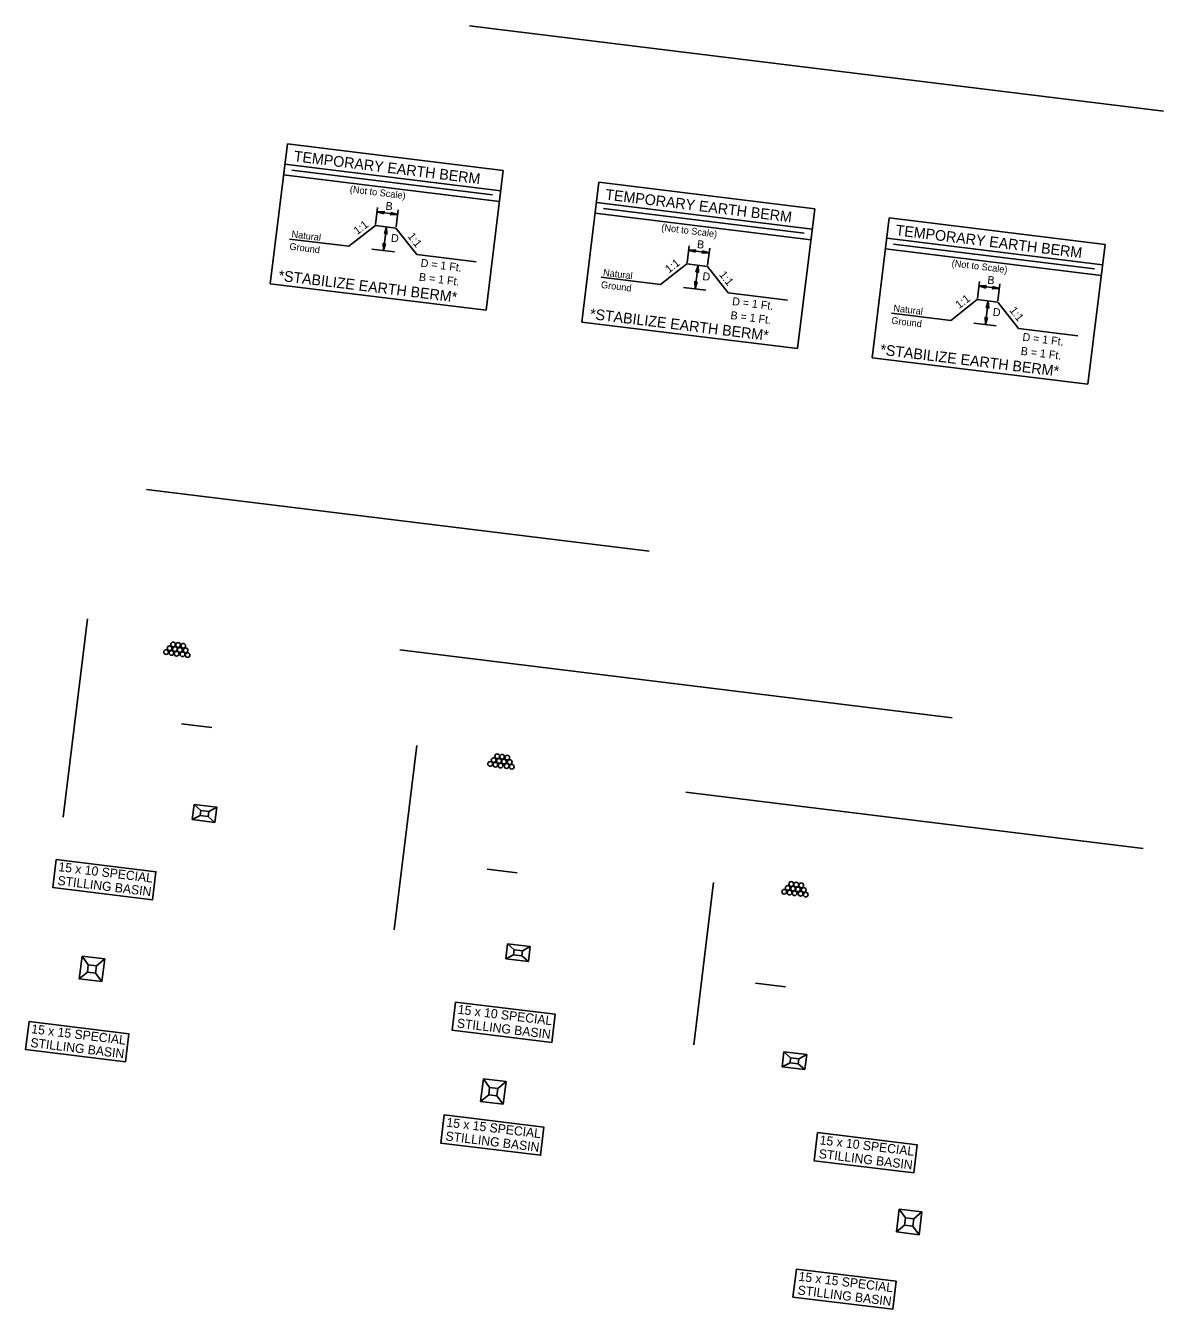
# Model space of a CAD drawing. Extents: x 2470000 to 2520000, y 340000 to 380000.
# Drawn here: x 2481272 to 2482019, y 373431 to 374273 of the extents above; entities that cross this region are included whole.
import ezdxf

# ---------------------------------------------------------------- set-up
doc = ezdxf.new("R2010")
doc.units = 0
for name, color, linetype in [('Earth Berm for Slope Drains Final', 7, 'Continuous'), ('Exist Property Owner Number CELL', 7, 'Continuous'), ('Exist Property Owner Text', 7, 'Continuous'), ('Exist Right of Way Easement Line', 7, 'Continuous'), ('Exist Right of Way Line', 7, 'Continuous'), ('Matchline', 7, 'Continuous'), ('Matchline Text', 7, 'Continuous'), ('Prop Dimension', 7, 'Continuous'), ('Prop Dimension Text', 7, 'Continuous'), ('Prop DSN Text', 7, 'Continuous'), ('Prop Grid Mask', 7, 'Continuous'), ('Prop Guardrail Attenuator CELL', 7, 'Continuous'), ('Prop Horizontal Alignment Tick Label', 7, 'Continuous'), ('Prop Lane Arrow CELL', 7, 'Continuous'), ('Prop Noise Wall', 7, 'Continuous'), ('Prop North Arrow NAD83 for Plan Sheets CELL', 7, 'Continuous'), ('Prop Superelevation  Arrow CELL', 7, 'Continuous'), ('Prop Superelevation Label', 7, 'Continuous'), ('Prop Terminator CELL', 7, 'Continuous'), ('Scratch_Level_5', 7, 'Continuous'), ('Scratch_Level_9', 7, 'Continuous'), ('Sheet Block Title CELL', 7, 'Continuous'), ('Sheet Sticker Incomplete CELL', 7, 'Continuous'), ('Sheet Sticker Preliminary CELL', 7, 'Continuous'), ('Special Stilling Basin 15 x 10 Note Final CELL', 7, 'Continuous'), ('Special Stilling Basin 15 x 15 Final CELL', 7, 'Continuous'), ('Special Stilling Basin 15 x 15 Note Both CELL', 7, 'Continuous'), ('Special Stilling Basin 15 x 15 Note Final CELL', 7, 'Continuous')]:
    doc.layers.add(name, color=color, linetype=linetype)

msp = doc.modelspace()

# ---------------------------------------------------------------- linework, layer by layer
at = {"layer": 'Earth Berm for Slope Drains Final'}
msp.add_line((2481705.55, 373770.06), (2482005.91, 373733.14), dxfattribs=at)
at = {"layer": 'Exist Property Owner Number CELL'}
msp.add_line((2481723.92, 373710.81), (2481710.8, 373604.14), dxfattribs=at)
at = {"layer": 'Exist Property Owner Text'}
for centre in [(2481774.85, 373709.75), (2481778.09, 373709.39), (2481770.22, 373704.69), (2481772.54, 373707.22), (2481773.72, 373704.15), (2481776.03, 373706.68), (2481777.07, 373703.64), (2481779.25, 373706.19), (2481781.01, 373703.31), (2481781.45, 373708.88), (2481783.05, 373705.88), (2481784.37, 373702.79)]:
    msp.add_circle(centre, 1.55, dxfattribs=at)
at = {"layer": 'Exist Right of Way Easement Line'}
msp.add_line((2481751.31, 373644.75), (2481771.16, 373642.31), dxfattribs=at)
at = {"layer": 'Exist Right of Way Line'}
for p, q in [((2481768.87, 373589.77), (2481770.1, 373599.7)), ((2481774.43, 373595.7), (2481770.1, 373599.7)), ((2481770.1, 373599.7), (2481784.99, 373597.86)), ((2481774.04, 373592.48), (2481774.43, 373595.7)), ((2481774.43, 373595.7), (2481779.82, 373595.01)), ((2481779.82, 373595.01), (2481779.43, 373591.81)), ((2481779.83, 373595.04), (2481784.99, 373597.86)), ((2481784.99, 373597.86), (2481783.77, 373587.94)), ((2481768.89, 373589.77), (2481774.08, 373592.46)), ((2481783.79, 373587.93), (2481768.89, 373589.77)), ((2481779.43, 373591.81), (2481774.08, 373592.46)), ((2481779.43, 373591.81), (2481783.77, 373587.94))]:
    msp.add_line(p, q, dxfattribs=at)
at = {"layer": 'Matchline'}
msp.add_line((2481312.82, 373883.8), (2481296.82, 373753.63), dxfattribs=at)
at = {"layer": 'Matchline Text'}
msp.add_line((2481374.5, 373814.87), (2481394.35, 373812.43), dxfattribs=at)
at = {"layer": 'Prop Dimension'}
msp.add_lwpolyline([(2481274.46, 373619.51), (2481339.97, 373611.46), (2481337.71, 373593.06), (2481272.2, 373601.11)], close=True, dxfattribs=at)
at = {"layer": 'Prop Dimension Text'}
for p, q in [((2481381.56, 373752.01), (2481382.79, 373761.94)), ((2481387.12, 373757.94), (2481382.79, 373761.94)), ((2481382.79, 373761.94), (2481397.67, 373760.1)), ((2481381.58, 373752.01), (2481386.77, 373754.7)), ((2481386.73, 373754.72), (2481387.12, 373757.94)), ((2481392.11, 373754.05), (2481386.77, 373754.7)), ((2481387.12, 373757.94), (2481392.51, 373757.25)), ((2481392.51, 373757.25), (2481392.11, 373754.05)), ((2481392.11, 373754.05), (2481396.46, 373750.18)), ((2481392.52, 373757.28), (2481397.67, 373760.1)), ((2481397.67, 373760.1), (2481396.46, 373750.18)), ((2481396.48, 373750.17), (2481381.58, 373752.01))]:
    msp.add_line(p, q, dxfattribs=at)
at = {"layer": 'Prop DSN Text'}
for centre in [(2481364.4, 373861.89), (2481366.71, 373864.42), (2481367.89, 373861.36), (2481369.02, 373866.95), (2481370.2, 373863.89), (2481371.25, 373860.84), (2481372.27, 373866.59), (2481373.43, 373863.39), (2481375.63, 373866.08), (2481377.23, 373863.08), (2481375.18, 373860.51), (2481378.54, 373859.99)]:
    msp.add_circle(centre, 1.55, dxfattribs=at)
at = {"layer": 'Prop Grid Mask'}
msp.add_lwpolyline([(2481292.26, 373725.86), (2481357.76, 373717.81), (2481355.5, 373699.41), (2481289.99, 373707.46)], close=True, dxfattribs=at)
at = {"layer": 'Prop Guardrail Attenuator CELL'}
msp.add_line((2481517.94, 373863.3), (2481880.55, 373818.73), dxfattribs=at)
at = {"layer": 'Prop Horizontal Alignment Tick Label'}
msp.add_line((2481575.12, 373719.42), (2481594.97, 373716.98), dxfattribs=at)
at = {"layer": 'Prop Lane Arrow CELL'}
for p, q in [((2481587.4, 373660.64), (2481588.63, 373670.57)), ((2481592.96, 373666.57), (2481588.63, 373670.57)), ((2481588.63, 373670.57), (2481603.52, 373668.73)), ((2481598.37, 373665.91), (2481603.52, 373668.73)), ((2481603.52, 373668.73), (2481602.31, 373658.81)), ((2481587.43, 373660.64), (2481592.61, 373663.33)), ((2481602.32, 373658.8), (2481587.43, 373660.64)), ((2481592.58, 373663.35), (2481592.96, 373666.57)), ((2481597.96, 373662.68), (2481592.61, 373663.33)), ((2481592.96, 373666.57), (2481598.35, 373665.88)), ((2481598.35, 373665.88), (2481597.96, 373662.68)), ((2481597.96, 373662.68), (2481602.31, 373658.81))]:
    msp.add_line(p, q, dxfattribs=at)
at = {"layer": 'Prop Noise Wall'}
for centre in [(2481581.8, 373793.61), (2481577.18, 373788.55), (2481579.49, 373791.08), (2481580.67, 373788.01), (2481582.98, 373790.54), (2481584.03, 373787.49), (2481585.05, 373793.25), (2481586.2, 373790.05), (2481587.96, 373787.16), (2481588.4, 373792.73), (2481590.01, 373789.74), (2481591.32, 373786.65)]:
    msp.add_circle(centre, 1.55, dxfattribs=at)
at = {"layer": 'Prop North Arrow NAD83 for Plan Sheets CELL'}
msp.add_line((2481351.57, 373968.69), (2481681.64, 373928.12), dxfattribs=at)
at = {"layer": 'Prop Superelevation  Arrow CELL'}
msp.add_lwpolyline([(2481554.46, 373632.28), (2481619.96, 373624.23), (2481617.7, 373605.83), (2481552.2, 373613.88)], close=True, dxfattribs=at)
at = {"layer": 'Prop Superelevation Label'}
for p, q in [((2481570.88, 373567.04), (2481572.72, 373581.93)), ((2481576.84, 373576.23), (2481572.72, 373581.93)), ((2481572.72, 373581.93), (2481587.61, 373580.09)), ((2481576.26, 373571.4), (2481576.84, 373576.23)), ((2481576.84, 373576.23), (2481582.23, 373575.52)), ((2481582.25, 373575.56), (2481587.61, 373580.09)), ((2481587.61, 373580.09), (2481585.79, 373565.2)), ((2481570.91, 373567.03), (2481576.29, 373571.37)), ((2481581.64, 373570.71), (2481576.29, 373571.37)), ((2481582.23, 373575.52), (2481581.64, 373570.71)), ((2481581.64, 373570.71), (2481585.79, 373565.2)), ((2481585.8, 373565.19), (2481570.91, 373567.03))]:
    msp.add_line(p, q, dxfattribs=at)
at = {"layer": 'Prop Terminator CELL'}
for p, q in [((2481307.37, 373647.55), (2481309.21, 373662.45)), ((2481313.33, 373656.74), (2481309.21, 373662.45)), ((2481309.21, 373662.45), (2481324.1, 373660.61)), ((2481318.73, 373656.08), (2481324.1, 373660.61)), ((2481324.1, 373660.61), (2481322.27, 373645.72)), ((2481307.4, 373647.55), (2481312.78, 373651.89)), ((2481312.75, 373651.91), (2481313.33, 373656.74)), ((2481318.13, 373651.23), (2481312.78, 373651.89)), ((2481313.33, 373656.74), (2481318.72, 373656.04)), ((2481318.72, 373656.04), (2481318.13, 373651.23)), ((2481322.29, 373645.71), (2481307.4, 373647.55)), ((2481318.13, 373651.23), (2481322.27, 373645.72))]:
    msp.add_line(p, q, dxfattribs=at)
at = {"layer": 'Scratch_Level_5'}
msp.add_line((2481529.11, 373800.58), (2481514.25, 373679.71), dxfattribs=at)
at = {"layer": 'Scratch_Level_9'}
for p, q in [((2481648.56, 374170.29), (2481637.28, 374078.49)), ((2481790.3, 374152.87), (2481648.56, 374170.29)), ((2481646.05, 374149.87), (2481787.79, 374132.45)), ((2481646.93, 374156.96), (2481788.66, 374139.54)), ((2481651.49, 374153.09), (2481783.3, 374136.89)), ((2481779.01, 374061.06), (2481790.3, 374152.87)), ((2481707.86, 374128.58), (2481706.48, 374117.4)), ((2481720.95, 374123.95), (2481707.49, 374125.6)), ((2481721.31, 374126.93), (2481719.94, 374115.77)), ((2481706.39, 374116.65), (2481689.04, 374103.04)), ((2481706.39, 374116.65), (2481719.85, 374115.03)), ((2481711.74, 374100.36), (2481713.64, 374115.78)), ((2481650.03, 374107.84), (2481689.04, 374103.04)), ((2481733.48, 374097.64), (2481719.85, 374115.03)), ((2481704.1, 374101.22), (2481718.88, 374099.41)), ((2481733.48, 374097.64), (2481772.49, 374092.85)), ((2481637.28, 374078.49), (2481779.01, 374061.06))]:
    msp.add_line(p, q, dxfattribs=at)
for points in [[(2481711.95, 374124.26), (2481707.49, 374125.6), (2481712.17, 374125.85), (2481711.49, 374125.11)], [(2481716.49, 374125.29), (2481720.95, 374123.95), (2481716.27, 374123.7), (2481716.95, 374124.44)], [(2481712.29, 374111.32), (2481713.64, 374115.78), (2481713.88, 374111.09), (2481713.15, 374111.78)], [(2481713.09, 374104.82), (2481711.74, 374100.36), (2481711.5, 374105.04), (2481712.24, 374104.36)]]:
    msp.add_lwpolyline(points, close=True, dxfattribs=at)
at = {"layer": 'Sheet Block Title CELL'}
for p, q in [((2481839.17, 374146.86), (2481827.88, 374055.06)), ((2481980.9, 374129.44), (2481839.17, 374146.86)), ((2481837.53, 374133.53), (2481979.26, 374116.11)), ((2481836.65, 374126.44), (2481978.39, 374109.02)), ((2481842.09, 374129.66), (2481973.9, 374113.46)), ((2481969.61, 374037.63), (2481980.9, 374129.44)), ((2481898.46, 374105.15), (2481897.08, 374093.97)), ((2481911.55, 374100.52), (2481898.09, 374102.17)), ((2481911.91, 374103.5), (2481910.54, 374092.34)), ((2481896.99, 374093.22), (2481879.64, 374079.61)), ((2481896.99, 374093.22), (2481910.45, 374091.6)), ((2481902.35, 374076.93), (2481904.24, 374092.35)), ((2481924.08, 374074.21), (2481910.45, 374091.6)), ((2481840.63, 374084.41), (2481879.64, 374079.61)), ((2481894.7, 374077.79), (2481909.48, 374075.98)), ((2481924.08, 374074.21), (2481963.09, 374069.42)), ((2481827.88, 374055.06), (2481969.61, 374037.63))]:
    msp.add_line(p, q, dxfattribs=at)
for points in [[(2481902.55, 374100.83), (2481898.09, 374102.17), (2481902.77, 374102.42), (2481902.09, 374101.68)], [(2481907.09, 374101.87), (2481911.55, 374100.52), (2481906.87, 374100.27), (2481907.55, 374101.01)], [(2481902.89, 374087.89), (2481904.24, 374092.35), (2481904.48, 374087.67), (2481903.75, 374088.35)], [(2481903.69, 374081.39), (2481902.35, 374076.93), (2481902.1, 374081.61), (2481902.84, 374080.93)]]:
    msp.add_lwpolyline(points, close=True, dxfattribs=at)
at = {"layer": 'Sheet Sticker Incomplete CELL'}
msp.add_line((2481563.58, 374272.97), (2482019.16, 374216.96), dxfattribs=at)
at = {"layer": 'Sheet Sticker Preliminary CELL'}
for p, q in [((2481444.02, 374195.44), (2481432.73, 374103.63)), ((2481585.75, 374178.01), (2481444.02, 374195.44)), ((2481441.51, 374175.01), (2481583.24, 374157.59)), ((2481442.38, 374182.1), (2481584.11, 374164.68)), ((2481446.94, 374178.24), (2481578.75, 374162.03)), ((2481574.47, 374086.21), (2481585.75, 374178.01)), ((2481503.31, 374153.72), (2481501.94, 374142.54)), ((2481516.4, 374149.09), (2481502.95, 374150.75)), ((2481516.77, 374152.07), (2481515.4, 374140.92)), ((2481501.84, 374141.8), (2481484.49, 374128.19)), ((2481501.84, 374141.8), (2481515.3, 374140.17)), ((2481507.2, 374125.5), (2481509.09, 374140.92)), ((2481445.49, 374132.98), (2481484.49, 374128.19)), ((2481528.94, 374122.78), (2481515.3, 374140.17)), ((2481499.55, 374126.37), (2481514.33, 374124.55)), ((2481528.94, 374122.78), (2481567.95, 374117.99)), ((2481432.73, 374103.63), (2481574.47, 374086.21))]:
    msp.add_line(p, q, dxfattribs=at)
for points in [[(2481507.4, 374149.4), (2481502.95, 374150.75), (2481507.63, 374150.99), (2481506.95, 374150.25)], [(2481511.94, 374150.44), (2481516.4, 374149.09), (2481511.72, 374148.85), (2481512.4, 374149.58)], [(2481507.75, 374136.46), (2481509.09, 374140.92), (2481509.34, 374136.24), (2481508.6, 374136.92)], [(2481508.54, 374129.96), (2481507.2, 374125.5), (2481506.95, 374130.18), (2481507.69, 374129.5)]]:
    msp.add_lwpolyline(points, close=True, dxfattribs=at)
at = {"layer": 'Special Stilling Basin 15 x 10 Note Final CELL'}
msp.add_lwpolyline([(2481792.07, 373546.58), (2481857.58, 373538.53), (2481855.32, 373520.13), (2481789.81, 373528.18)], close=True, dxfattribs=at)
at = {"layer": 'Special Stilling Basin 15 x 15 Final CELL'}
for p, q in [((2481843.89, 373481.47), (2481845.73, 373496.37)), ((2481849.85, 373490.66), (2481845.73, 373496.37)), ((2481845.73, 373496.37), (2481860.62, 373494.53)), ((2481855.26, 373490), (2481860.62, 373494.53)), ((2481860.62, 373494.53), (2481858.8, 373479.64)), ((2481843.92, 373481.47), (2481849.3, 373485.81)), ((2481849.27, 373485.83), (2481849.85, 373490.66)), ((2481854.65, 373485.15), (2481849.3, 373485.81)), ((2481849.85, 373490.66), (2481855.24, 373489.96)), ((2481855.24, 373489.96), (2481854.65, 373485.15)), ((2481854.65, 373485.15), (2481858.8, 373479.64)), ((2481858.81, 373479.63), (2481843.92, 373481.47))]:
    msp.add_line(p, q, dxfattribs=at)
at = {"layer": 'Special Stilling Basin 15 x 15 Note Both CELL'}
msp.add_lwpolyline([(2481547.01, 373558.18), (2481612.52, 373550.13), (2481610.26, 373531.73), (2481544.75, 373539.79)], close=True, dxfattribs=at)
at = {"layer": 'Special Stilling Basin 15 x 15 Note Final CELL'}
msp.add_lwpolyline([(2481778.22, 373457.1), (2481843.73, 373449.05), (2481841.47, 373430.65), (2481775.96, 373438.7)], close=True, dxfattribs=at)

# ---------------------------------------------------------------- texts
at = {"layer": 'Prop Dimension'}
for s, p in [('15 x 15 SPECIAL', (2481275.64, 373611.86)), ('STILLING BASIN', (2481275.06, 373602.87))]:
    msp.add_text(s, height=6, rotation=352.99213, dxfattribs=at).set_placement(p)
at = {"layer": 'Prop Grid Mask'}
for s, p in [('15 x 10 SPECIAL', (2481293.44, 373718.22)), ('STILLING BASIN', (2481292.85, 373709.22))]:
    msp.add_text(s, height=6, rotation=352.99213, dxfattribs=at).set_placement(p)
at = {"layer": 'Prop Superelevation  Arrow CELL'}
for s, p in [('15 x 10 SPECIAL', (2481555.64, 373624.64)), ('STILLING BASIN', (2481555.05, 373615.64))]:
    msp.add_text(s, height=6, rotation=352.99213, dxfattribs=at).set_placement(p)
at = {"layer": 'Scratch_Level_9'}
for s, height, rotation, p in [('TEMPORARY EARTH BERM', 7, 352.99213, (2481652.49, 374158.89)), ('(Not to Scale)', 4.5, 352.99213, (2481689.4, 374138.48)), ('B', 5.25, 352.99213, (2481712.78, 374127.13)), ('1:1', 5.25, 37.09557, (2481694.5, 374110.39)), ('Natural ', 4.5, 352.99213, (2481651.13, 374108.96)), ('D', 5.25, 352.99213, (2481716.33, 374106.09)), ('1:1', 5.25, 308.10746, (2481727.21, 374109.49)), ('Ground', 4.5, 352.99213, (2481649.77, 374100.9)), ('D = 1 Ft.', 5.25, 352.99213, (2481735.85, 374089.67)), ('*STABILIZE EARTH BERM*', 7, 352.99213, (2481642.42, 374080.57)), ('B = 1 Ft.', 5.25, 352.99213, (2481734.72, 374080.49))]:
    msp.add_text(s, height=height, rotation=rotation, dxfattribs=at).set_placement(p)
at = {"layer": 'Sheet Block Title CELL'}
for s, height, rotation, p in [('TEMPORARY EARTH BERM', 7, 352.99213, (2481843.09, 374135.46)), ('(Not to Scale)', 4.5, 352.99213, (2481880, 374115.05)), ('B', 5.25, 352.99213, (2481903.38, 374103.7)), ('Natural ', 4.5, 352.99213, (2481841.73, 374085.53)), ('1:1', 5.25, 37.09557, (2481885.1, 374086.96)), ('Ground', 4.5, 352.99213, (2481840.37, 374077.47)), ('D', 5.25, 352.99213, (2481906.93, 374082.67)), ('1:1', 5.25, 308.10746, (2481917.81, 374086.06)), ('D = 1 Ft.', 5.25, 352.99213, (2481926.45, 374066.24)), ('*STABILIZE EARTH BERM*', 7, 352.99213, (2481833.02, 374057.14)), ('B = 1 Ft.', 5.25, 352.99213, (2481925.32, 374057.06))]:
    msp.add_text(s, height=height, rotation=rotation, dxfattribs=at).set_placement(p)
at = {"layer": 'Sheet Sticker Preliminary CELL'}
for s, height, rotation, p in [('TEMPORARY EARTH BERM', 7, 352.99213, (2481447.95, 374184.03)), ('(Not to Scale)', 4.5, 352.99213, (2481484.86, 374163.63)), ('B', 5.25, 352.99213, (2481508.23, 374152.27)), ('1:1', 5.25, 37.09557, (2481489.95, 374135.54)), ('Natural ', 4.5, 352.99213, (2481446.58, 374134.11)), ('D', 5.25, 352.99213, (2481511.78, 374131.24)), ('1:1', 5.25, 308.10746, (2481522.66, 374134.63)), ('Ground', 4.5, 352.99213, (2481445.22, 374126.04)), ('D = 1 Ft.', 5.25, 352.99213, (2481531.3, 374114.81)), ('*STABILIZE EARTH BERM*', 7, 352.99213, (2481437.87, 374105.72)), ('B = 1 Ft.', 5.25, 352.99213, (2481530.18, 374105.63))]:
    msp.add_text(s, height=height, rotation=rotation, dxfattribs=at).set_placement(p)
at = {"layer": 'Special Stilling Basin 15 x 10 Note Final CELL'}
for s, p in [('15 x 10 SPECIAL', (2481793.25, 373538.94)), ('STILLING BASIN', (2481792.66, 373529.94))]:
    msp.add_text(s, height=6, rotation=352.99213, dxfattribs=at).set_placement(p)
at = {"layer": 'Special Stilling Basin 15 x 15 Note Both CELL'}
for s, p in [('15 x 15 SPECIAL', (2481548.19, 373550.54)), ('STILLING BASIN', (2481547.61, 373541.54))]:
    msp.add_text(s, height=6, rotation=352.99213, dxfattribs=at).set_placement(p)
at = {"layer": 'Special Stilling Basin 15 x 15 Note Final CELL'}
for s, p in [('15 x 15 SPECIAL', (2481779.4, 373449.45)), ('STILLING BASIN', (2481778.81, 373440.46))]:
    msp.add_text(s, height=6, rotation=352.99213, dxfattribs=at).set_placement(p)

doc.saveas('drawing.dxf')
